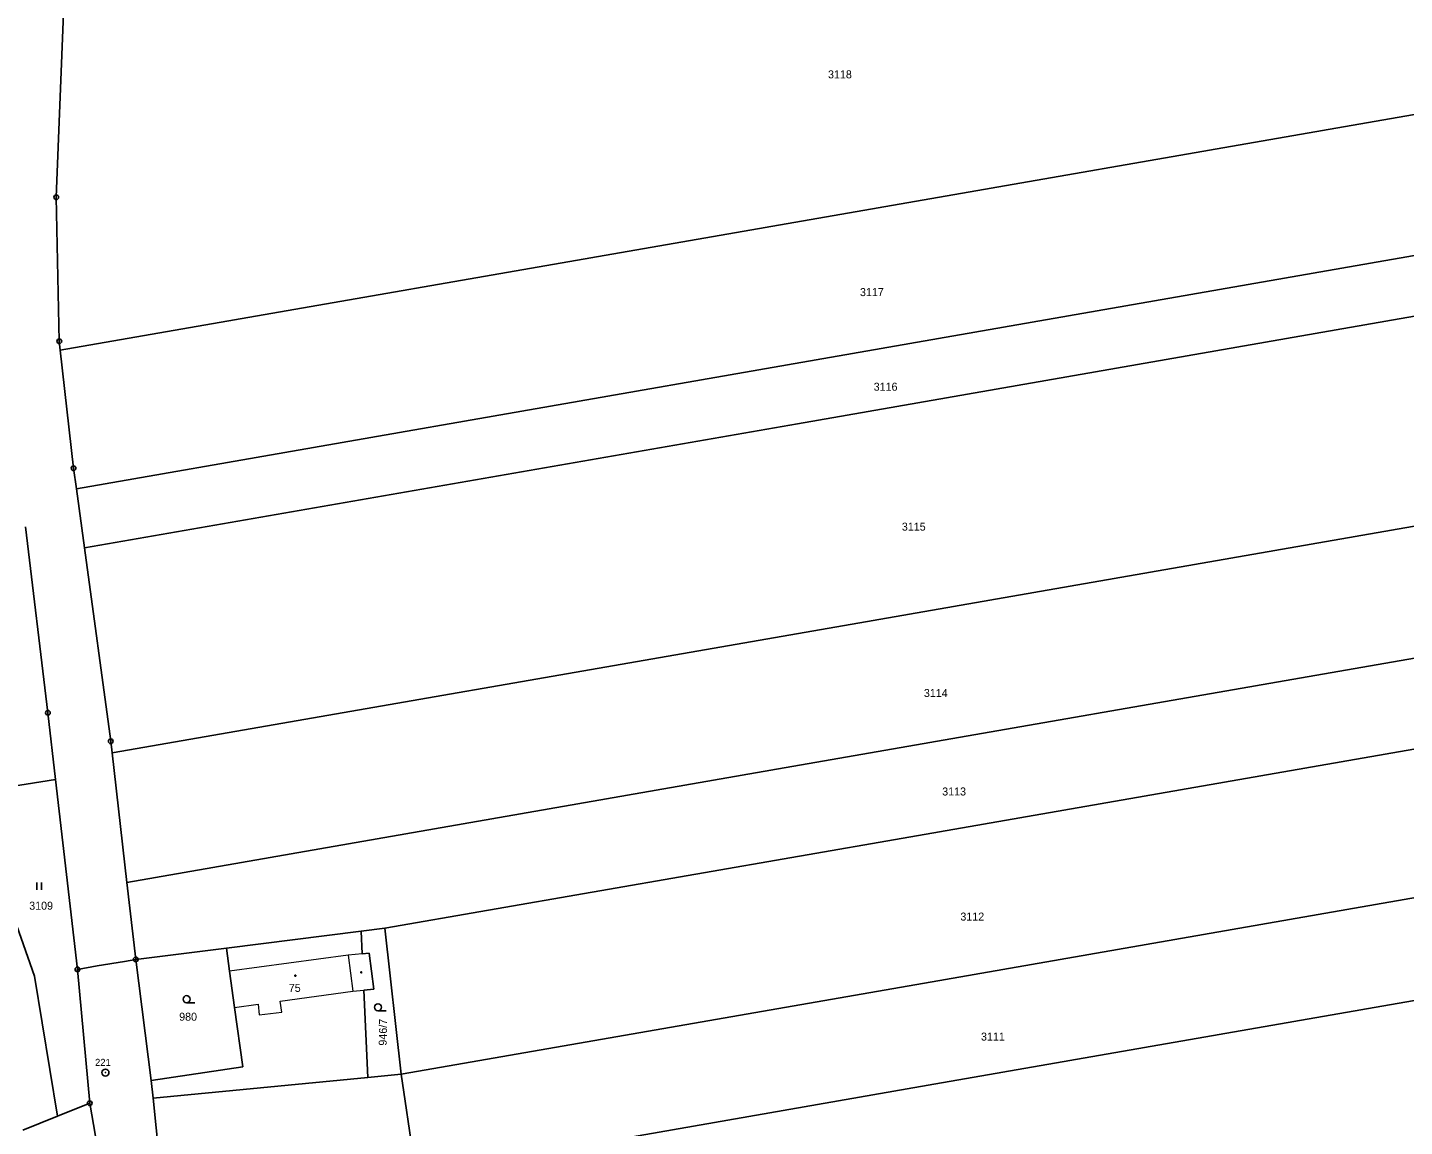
# Model space of a CAD drawing. Extents: x -618848 to -615803, y -1044450 to -1042254.
# Drawn here: x -617038.7 to -616746.1, y -1042756.5 to -1042523.1 of the extents above; entities that cross this region are included whole.
import ezdxf
from ezdxf.enums import TextEntityAlignment as Align

# ---------------------------------------------------------------- set-up
doc = ezdxf.new("R2010")
doc.units = 0
doc.header["$LTSCALE"] = 0.68
for name, color, linetype, lineweight in [('1', 7, 'Continuous', 25), ('3', 7, 'Continuous', 25), ('4', 7, 'Continuous', 13), ('5', 7, 'Continuous', 25), ('8', 7, 'Continuous', 25)]:
    doc.layers.add(name, color=color, linetype=linetype, lineweight=lineweight)
doc.layers.add('2', color=7, linetype='Continuous')

msp = doc.modelspace()

# ---------------------------------------------------------------- linework, layer by layer
at = {"layer": '1'}
for p, q in [((-617032.56, -1042559.13), (-617030.97, -1042518.3)), ((-616881.92, -1042565.54), (-616732.14, -1042539.47)), ((-617031.92, -1042589.74), (-617032.56, -1042559.13)), ((-617031.71, -1042591.62), (-616881.92, -1042565.54)), ((-616726.13, -1042568.43), (-616877.21, -1042594.74)), ((-616875.06, -1042607.25), (-616723.55, -1042580.87)), ((-617031.71, -1042591.62), (-617031.92, -1042589.74)), ((-617028.88, -1042616.7), (-617031.71, -1042591.62)), ((-616877.21, -1042594.74), (-617028.29, -1042621.04)), ((-617026.58, -1042633.63), (-616875.06, -1042607.25)), ((-617028.29, -1042621.04), (-617028.88, -1042616.7)), ((-617026.58, -1042633.63), (-617028.29, -1042621.04)), ((-616715.93, -1042624.13), (-616868.32, -1042650.66)), ((-617039.11, -1042629.12), (-617034.33, -1042668.64)), ((-617020.98, -1042674.7), (-617026.58, -1042633.63)), ((-616868.32, -1042650.66), (-617020.7, -1042677.18)), ((-616880.76, -1042680.86), (-616743.98, -1042657.04)), ((-617034.33, -1042668.64), (-617032.7, -1042682.79)), ((-617020.7, -1042677.18), (-617020.98, -1042674.7)), ((-617017.55, -1042704.68), (-617020.7, -1042677.18)), ((-616742.5, -1042676.07), (-616852.62, -1042695.24)), ((-617017.55, -1042704.68), (-616880.76, -1042680.86)), ((-617032.7, -1042682.79), (-617050.29, -1042685.56)), ((-617028.08, -1042723.13), (-617032.7, -1042682.79)), ((-617047.48, -1042695.46), (-617037.18, -1042724.56)), ((-616852.62, -1042695.24), (-616962.73, -1042714.41)), ((-617015.68, -1042721.03), (-617017.55, -1042704.68)), ((-616849.7, -1042726.32), (-616740.09, -1042707.24)), ((-616996.42, -1042718.62), (-616967.79, -1042715.04)), ((-616962.73, -1042714.41), (-616967.79, -1042715.04)), ((-616967.79, -1042715.04), (-616967.57, -1042719.84)), ((-616959.32, -1042745.4), (-616962.73, -1042714.41)), ((-617015.68, -1042721.03), (-616996.42, -1042718.62)), ((-616996.42, -1042718.62), (-616995.74, -1042723.53)), ((-617018.07, -1042721.43), (-617023.87, -1042722.42)), ((-617015.68, -1042721.03), (-617018.07, -1042721.43)), ((-617012.43, -1042746.75), (-617015.68, -1042721.03)), ((-616967.57, -1042719.84), (-616966.08, -1042719.69)), ((-616966.08, -1042719.69), (-616965.08, -1042727.34)), ((-617037.18, -1042724.56), (-617032.32, -1042754.32)), ((-617023.87, -1042722.42), (-617028.08, -1042723.13)), ((-617028.08, -1042723.13), (-617025.46, -1042751.56)), ((-616995.74, -1042723.53), (-616994.68, -1042731.23)), ((-616965.08, -1042727.34), (-616967.21, -1042727.55)), ((-616967.21, -1042727.55), (-616966.36, -1042746.09)), ((-616959.32, -1042745.4), (-616849.7, -1042726.32)), ((-616738.42, -1042728.8), (-616847.28, -1042747.74)), ((-616994.68, -1042731.23), (-616992.95, -1042743.81)), ((-617012.43, -1042746.75), (-616992.95, -1042743.81)), ((-617012.43, -1042746.75), (-617011.98, -1042750.47)), ((-616966.36, -1042746.09), (-617011.98, -1042750.47)), ((-616959.32, -1042745.4), (-616966.36, -1042746.09)), ((-616959.32, -1042745.4), (-616956.3, -1042765.59)), ((-616847.28, -1042747.74), (-616956.15, -1042766.69)), ((-617011.98, -1042750.47), (-617009.97, -1042770.22)), ((-617025.46, -1042751.56), (-617032.32, -1042754.32)), ((-617021.87, -1042772.46), (-617025.46, -1042751.56)), ((-617032.32, -1042754.32), (-617039.67, -1042757.28))]:
    msp.add_line(p, q, dxfattribs=at)
at = {"layer": '3'}
for p, q in [((-617036.711, -1042706.22), (-617036.711, -1042704.72)), ((-617035.71, -1042706.22), (-617035.71, -1042704.72)), ((-617004.873, -1042730.22), (-617003.123, -1042730.22)), ((-616964.213, -1042731.94), (-616962.463, -1042731.94))]:
    msp.add_line(p, q, dxfattribs=at)
for centre in [(-617004.8729, -1042729.4698), (-616964.2129, -1042731.1898)]:
    msp.add_circle(centre, 0.75, dxfattribs=at)
at = {"layer": '4'}
for p, q in [((-616970.54, -1042720.13), (-616995.74, -1042723.53)), ((-616994.68, -1042731.23), (-616989.7, -1042730.55)), ((-616989.7, -1042730.55), (-616989.43, -1042732.82)), ((-616984.97, -1042729.89), (-616969.54, -1042727.77)), ((-616984.62, -1042732.2), (-616984.97, -1042729.89)), ((-616989.43, -1042732.82), (-616984.62, -1042732.2))]:
    msp.add_line(p, q, dxfattribs=at)
msp.add_lwpolyline([(-616967.57, -1042719.84), (-616970.54, -1042720.13), (-616969.54, -1042727.77), (-616967.21, -1042727.55)], dxfattribs=at)
at = {"layer": '5'}
for centre in [(-616981.7746, -1042724.4794), (-616967.7646, -1042723.7594)]:
    msp.add_circle(centre, 0.1172, dxfattribs=at)
at = {"layer": '8'}
for centre, radius in [((-617032.56, -1042559.1299), 0.5), ((-617032.56, -1042559.1299), 0.0303), ((-617031.92, -1042589.7399), 0.5), ((-617031.92, -1042589.7399), 0.0303), ((-617028.88, -1042616.6999), 0.5), ((-617028.88, -1042616.6999), 0.0303), ((-617034.33, -1042668.6399), 0.5), ((-617034.33, -1042668.6399), 0.0303), ((-617020.98, -1042674.6999), 0.5), ((-617020.98, -1042674.6999), 0.0303), ((-617015.68, -1042721.0299), 0.5), ((-617015.68, -1042721.0299), 0.0303), ((-617028.08, -1042723.1299), 0.5), ((-617028.08, -1042723.1299), 0.0303), ((-617022.12, -1042745.0598), 0.75), ((-617022.12, -1042745.0598), 0.03), ((-617025.46, -1042751.5599), 0.5), ((-617025.46, -1042751.5599), 0.0303)]:
    msp.add_circle(centre, radius, dxfattribs=at)

# ---------------------------------------------------------------- texts
at = {"layer": '2'}
for s, p in [('3118', (-616868.59, -1042533.895)), ('3117', (-616861.8, -1042580.135)), ('3116', (-616858.89, -1042600.235)), ('3115', (-616852.9, -1042629.955)), ('3114', (-616848.22, -1042665.285)), ('3113', (-616844.33, -1042686.205)), ('3109', (-617038.32, -1042710.465)), ('3112', (-616840.47, -1042712.775)), ('3111', (-616836.09, -1042738.265))]:
    msp.add_text(s, height=1.7, dxfattribs=at).set_placement(p)
for s, p in [('75', (-616981.899, -1042727.925)), ('980', (-617004.559, -1042734.045))]:
    msp.add_text(s, height=1.7, dxfattribs=at).set_placement(p, align=Align.CENTER)
msp.add_text('946/7', height=1.7, rotation=89, dxfattribs=at).set_placement((-616962.3144, -1042736.4998), align=Align.CENTER)
at = {"layer": '8'}
msp.add_text('221', height=1.5, dxfattribs=at).set_placement((-617020.982, -1042743.642), align=Align.RIGHT)

doc.saveas('drawing.dxf')
